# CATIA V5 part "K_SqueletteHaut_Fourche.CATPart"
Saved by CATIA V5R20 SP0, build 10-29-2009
Part number: Squelette_Haut_Fourche
Bounding box of the stored display mesh (mm): x -85.682 to 119.621, y -56.23 to 41.338, z -450.118 to -110
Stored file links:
  G:\Khaled_CFAO_2011\ST2M\ST2M_GR1\bmartinez\Khaled\CAD_ThinkMOTION\K_SqueletteHaut_Fourche.CATPart
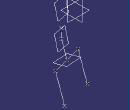
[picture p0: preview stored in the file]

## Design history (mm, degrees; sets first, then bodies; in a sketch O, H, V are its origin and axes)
Set1
  Point1: type OnCurve, Support Line1, Length 60
  Line1: stored without definition
  Line2: type PtDir, RefPoint Point1, Direction Line3, Start 60, End 20
  Line3: stored without definition
  Point2: type OnCurve, Support Line2, Length 40
  Plane1: type Angle, RefPlane Plane2, Direction Line4, Angle 15
  Line4: stored without definition
  Plane2: stored without definition
  Plane3: type OffsetPt, RefPlane Plane1, RefPoint Point2
  Point3: type OnPlane, Support Plane3, RefPoint Point2, H 0, V -110, Direction (-0.9686, -0.2487, 0)
  Line5: type PtPt, FirstPoint Point2, SecondPoint Point3
  Point4: type OnPlane, Support Plane3, RefPoint Point2, H 100, V -110, Direction (-0.9686, -0.2487, 0)
  Point5: type OnPlane, Support Plane3, RefPoint Point2, H -100, V -110, Direction (-0.9686, -0.2487, 0)
  Line6: type PtPt, FirstPoint Point5, SecondPoint Point4
  Plane4: type Angle, RefPlane Plane3, Direction Line6, Angle 90
  Line7: type PtDir, RefPoint Point5, Direction Plane4, Start 0, End 180
  Line8: type PtDir, RefPoint Point4, Direction Plane4, Start 0, End 180
  Point6: type OnCurve, Support Line8, Length 180
  Point7: type OnCurve, Support Line7, Length 180
Body1 (main body)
